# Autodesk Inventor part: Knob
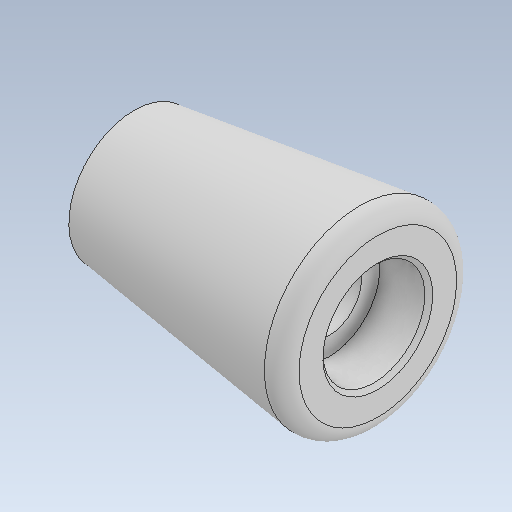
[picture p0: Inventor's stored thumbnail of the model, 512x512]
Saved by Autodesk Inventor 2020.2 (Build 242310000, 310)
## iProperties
Created: 2020-01
Part Number: Knob
Material: Generic
Document SubType Name: Modeling
Designer: Patrick Everitt
Density: 1 g/cm^3
Appearance: Default
Description: 2 Dia 2 Lg
Author: Patrick Everitt
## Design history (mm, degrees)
sketch "Sketch1"
  geometry: L1 (0, 6.35)-(0, 12.7); L2 (0, 12.7)-(47.371, 18.937); L3 (0, 6.35)-(37.846, 6.35); L4 (37.846, 6.35)-(37.846, 9.906); L5 (37.846, 9.906)-(47.371, 9.906); L6 (47.371, 18.937)-(47.371, 9.906); L7 (-2.54, 0)-(51.915, 0); L8 (-2.54, 0)-(-2.54, 12.366); 1 further point
  constraints: 16 end point, 2 horizontal, 2 parallel, 2 perpendicular, 1 point on line, 1 vertical
  dimensions: "d0" = 12.7 distance of L1.end point (0, 0); "d5" = 37.846 distance of L1.start L3.end; "d10" = 47.371 horizontal distance of L5.end L1.start; "d18" = 6.35 distance of L1.start point (0, 0); "d19" = 9.906 vertical distance of L5.end point (0, 0); "d22" = 6.35 distance from line of L3 point (0, 0); "d23" = 18.93651 vertical distance of L2.end point (0, 0); "d29" = 12.3656 distance of L7.start L8.end
revolve "Revolution1" sketch "Sketch1" stored, may be unused: angle "d21" = 90 deg
fillet "Fillet1" dims "d24" = 3.175
chamfer "Chamfer1" distance "d25" = 0.762; stored, may be unused: second distance "d26" = 3.175, angle "d27" = 45 deg
body "Solid1"
